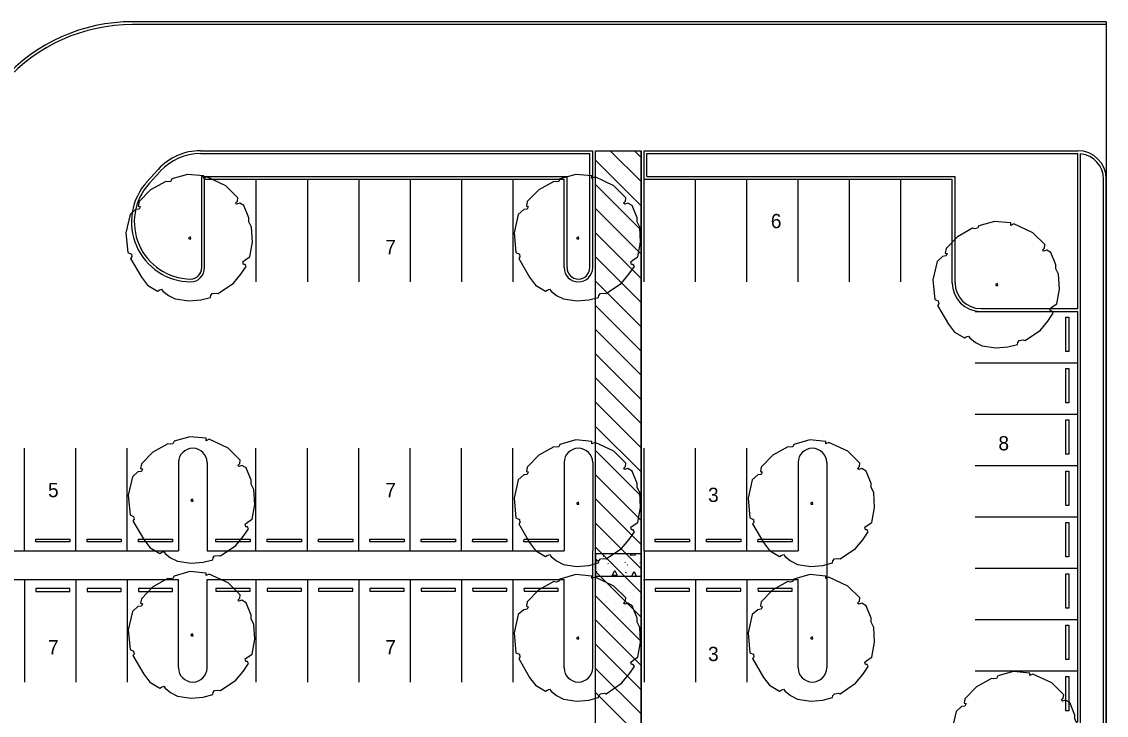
# Model space of a CAD drawing. Extents: x 6712138 to 6712574, y 1869536 to 1870160.
# Drawn here: x 6712370.5 to 6712560.6, y 1870038.8 to 1870160.5 of the extents above; entities that cross this region are included whole.
import ezdxf

# ---------------------------------------------------------------- set-up
doc = ezdxf.new("R2010")
doc.units = 0
for name, color, linetype in [('A-ANNO-TEXT', 7, 'Continuous'), ('A-FLOR-CASE', 7, 'Continuous'), ('A-FLOR-HRAL', 7, 'Continuous'), ('A-FLOR-PATT', 7, 'Continuous'), ('A-WALL-MBNI', 7, 'Continuous'), ('C-Boun-Imaginary', 7, 'Continuous'), ('C-PRKG-CONC', 7, 'Continuous'), ('C-PRKG-STRP', 7, 'Continuous'), ('L-tree', 7, 'Continuous')]:
    doc.layers.add(name, color=color, linetype=linetype)

# ---------------------------------------------------------------- blocks, each defined once
blk = doc.blocks.new('TREE 1')
at = {"layer": 'L-tree'}
for p, q in [((-0.2231, 0.5104), (-0.357, 0.4356)), ((-0.2025, 0.506), (-0.2231, 0.5104)), ((-0.1785, 0.5104), (-0.2025, 0.506)), ((-0.1682, 0.5324), (-0.1785, 0.5104)), ((-0.0275, 0.572), (-0.1682, 0.5324)), ((0.1167, 0.5588), (-0.0275, 0.572)), ((0.1167, 0.5368), (0.1167, 0.5588)), ((0.1441, 0.55), (0.1167, 0.5368)), ((0.3123, 0.4708), (0.1441, 0.55)), ((-0.357, 0.4356), (-0.4599, 0.33)), ((0.4187, 0.3652), (0.3123, 0.4708)), ((-0.4599, 0.33), (-0.4668, 0.2904)), ((-0.4668, 0.2904), (-0.4496, 0.286)), ((0.3981, 0.3168), (0.4153, 0.3344)), ((0.4084, 0.308), (0.3981, 0.3168)), ((0.4359, 0.3168), (0.4084, 0.308)), ((0.4153, 0.3344), (0.4187, 0.3652)), ((0.4737, 0.2948), (0.4359, 0.3168)), ((0.5183, 0.1848), (0.4737, 0.2948)), ((-0.5389, 0.2156), (-0.5766, 0.0528)), ((-0.4908, 0.2596), (-0.5389, 0.2156)), ((-0.4599, 0.264), (-0.4908, 0.2596)), ((-0.4496, 0.286), (-0.4599, 0.264)), ((0.5183, 0.1496), (0.5183, 0.1848)), ((0.5423, 0.1012), (0.5183, 0.1496)), ((0.5492, -0.0308), (0.5423, 0.1012)), ((-0.5766, 0.0528), (-0.5595, -0.1232)), ((-0.0034, 0.0176), (-0.0206, 0.0088)), ((-0.0206, 0.0088), (-0.0137, 0)), ((-0.0137, 0), (0, 0)), ((0, 0), (-0.0034, 0.0176)), ((0.5251, -0.1628), (0.5492, -0.0308)), ((-0.5595, -0.1232), (-0.5286, -0.1364)), ((-0.5251, -0.1628), (-0.5354, -0.176)), ((-0.5354, -0.176), (-0.4393, -0.3432)), ((-0.5286, -0.1364), (-0.5251, -0.1628)), ((0.4634, -0.2068), (0.4839, -0.1892)), ((0.4839, -0.1892), (0.5251, -0.1628)), ((0.4462, -0.3168), (0.4942, -0.2464)), ((0.4702, -0.2288), (0.4634, -0.2068)), ((0.4839, -0.2288), (0.4702, -0.2288)), ((0.4942, -0.2464), (0.4839, -0.2288)), ((-0.4393, -0.3432), (-0.3844, -0.4136)), ((0.381, -0.396), (0.4462, -0.3168)), ((-0.3844, -0.4136), (-0.2952, -0.4664)), ((-0.2952, -0.4664), (-0.2815, -0.4576)), ((-0.2815, -0.4576), (-0.2609, -0.4488)), ((-0.2609, -0.4488), (-0.2471, -0.4664)), ((-0.2471, -0.4664), (-0.1991, -0.506)), ((0.2437, -0.4884), (0.381, -0.396)), ((-0.1991, -0.506), (-0.1373, -0.5368)), ((-0.1373, -0.5368), (-0.0172, -0.5544)), ((-0.0172, -0.5544), (0.0892, -0.5456)), ((0.0892, -0.5456), (0.175, -0.5236)), ((0.175, -0.5236), (0.1785, -0.506)), ((0.1785, -0.506), (0.1922, -0.4884)), ((0.1922, -0.4884), (0.2265, -0.484)), ((0.2265, -0.484), (0.2437, -0.4884))]:
    blk.add_line(p, q, dxfattribs=at)

msp = doc.modelspace()

# ---------------------------------------------------------------- linework, layer by layer
at = {"layer": 'A-FLOR-CASE'}
msp.add_lwpolyline([(6712471.06, 1869725.57), (6712471.06, 1870137.85), (6712479.06, 1870137.85), (6712479.06, 1869725.57)], close=True, dxfattribs=at)
at = {"layer": 'A-FLOR-HRAL'}
msp.add_line((6712560.56, 1870159.97), (6712560.56, 1869926.78), dxfattribs=at)
at = {"layer": 'A-FLOR-PATT'}
for p, q in [((6712472.37, 1870066.79), (6712472.43, 1870066.68)), ((6712476.21, 1870065.78), (6712476.28, 1870065.66)), ((6712478.81, 1870065.68), (6712478.88, 1870065.58)), ((6712471.22, 1870064.02), (6712471.29, 1870064.18)), ((6712473.22, 1870065.5), (6712473.29, 1870065.4)), ((6712476.35, 1870063.84), (6712476.42, 1870064)), ((6712476.59, 1870065.28), (6712476.66, 1870065.17))]:
    msp.add_line(p, q, dxfattribs=at)
for points in [[(6712471.06, 1870066.05), (6712471.13, 1870066.22), (6712471.49, 1870065.95), (6712471.06, 1870065.82)], [(6712473.82, 1870067.1), (6712473.85, 1870067.17)], [(6712474.57, 1870067.17), (6712473.84, 1870067.1)], [(6712477.19, 1870066.88), (6712477.34, 1870067.17)], [(6712477.94, 1870067.17), (6712478.03, 1870066.95), (6712477.21, 1870066.88)], [(6712473.99, 1870063.37), (6712474.46, 1870064.26), (6712474.83, 1870063.44), (6712474.01, 1870063.37)], [(6712477.37, 1870063.17), (6712477.83, 1870064.04), (6712478.2, 1870063.22), (6712477.65, 1870063.17)]]:
    msp.add_lwpolyline(points, dxfattribs=at)
at = {"layer": 'A-WALL-MBNI'}
for p, q in [((6712479.06, 1870067.17), (6712471.06, 1870067.17)), ((6712471.06, 1870067.17), (6712471.06, 1870063.17)), ((6712479.06, 1870067.17), (6712479.06, 1870063.17)), ((6712479.06, 1870063.17), (6712471.06, 1870063.17))]:
    msp.add_line(p, q, dxfattribs=at)
at = {"layer": 'C-Boun-Imaginary'}
msp.add_line((6712560.56, 1870159.97), (6712560.56, 1869926.78), dxfattribs=at)
msp.add_line((6712560.56, 1870159.97), (6712560.56, 1869926.78), dxfattribs=at)
at = {"layer": 'C-PRKG-CONC'}
for p, q in [((6712560.56, 1870160.47), (6712389.92, 1870160.47)), ((6712560.56, 1870159.97), (6712389.92, 1870159.97)), ((6712560.56, 1870160.47), (6712560.56, 1870159.97)), ((6712401.83, 1870137.85), (6712470.56, 1870137.85)), ((6712470.56, 1870132.85), (6712470.56, 1870137.85)), ((6712479.56, 1870132.85), (6712479.56, 1870137.85)), ((6712479.56, 1870137.85), (6712555.56, 1870137.85)), ((6712401.83, 1870137.35), (6712470.06, 1870137.35)), ((6712470.06, 1870117.35), (6712470.06, 1870137.35)), ((6712480.06, 1870133.35), (6712480.06, 1870137.35)), ((6712480.06, 1870137.35), (6712555.56, 1870137.35)), ((6712555.56, 1870110.17), (6712555.56, 1870137.35)), ((6712556.06, 1870037.17), (6712556.06, 1870137.32)), ((6712394.43, 1870134.57), (6712392.46, 1870132.4)), ((6712394.8, 1870134.23), (6712392.83, 1870132.07)), ((6712402.06, 1870133.35), (6712466.06, 1870133.35)), ((6712402.06, 1870117.35), (6712402.06, 1870133.35)), ((6712402.56, 1870132.85), (6712465.56, 1870132.85)), ((6712402.56, 1870117.35), (6712402.56, 1870132.85)), ((6712411.56, 1870132.85), (6712411.56, 1870114.85)), ((6712420.56, 1870132.85), (6712420.56, 1870114.85)), ((6712429.56, 1870132.85), (6712429.56, 1870114.85)), ((6712438.56, 1870132.85), (6712438.56, 1870114.85)), ((6712447.56, 1870132.85), (6712447.56, 1870114.85)), ((6712456.56, 1870132.85), (6712456.56, 1870114.85)), ((6712465.56, 1870117.35), (6712465.56, 1870132.85)), ((6712466.06, 1870117.35), (6712466.06, 1870133.35)), ((6712470.56, 1870117.35), (6712470.56, 1870132.85)), ((6712479.56, 1870132.85), (6712533.56, 1870132.85)), ((6712479.56, 1870114.85), (6712479.56, 1870132.85)), ((6712480.06, 1870133.35), (6712534.06, 1870133.35)), ((6712488.56, 1870114.85), (6712488.56, 1870132.85)), ((6712497.56, 1870114.85), (6712497.56, 1870132.85)), ((6712506.56, 1870114.85), (6712506.56, 1870132.85)), ((6712515.56, 1870114.85), (6712515.56, 1870132.85)), ((6712524.56, 1870114.85), (6712524.56, 1870132.85)), ((6712533.56, 1870114.6), (6712533.56, 1870132.85)), ((6712534.06, 1870114.6), (6712534.06, 1870133.35)), ((6712560.05, 1869930.11), (6712560.06, 1870132.85)), ((6712560.55, 1869930.11), (6712560.56, 1870132.85)), ((6712537.56, 1870109.67), (6712555.56, 1870109.67)), ((6712538.56, 1870110.17), (6712555.56, 1870110.17)), ((6712538.56, 1870109.67), (6712555.56, 1870109.67)), ((6712555.56, 1870037.67), (6712555.56, 1870109.67)), ((6712553.47, 1870108.64), (6712553.97, 1870108.64)), ((6712553.47, 1870102.64), (6712553.47, 1870108.64)), ((6712553.97, 1870108.64), (6712553.97, 1870102.64)), ((6712553.97, 1870102.64), (6712553.47, 1870102.64)), ((6712537.56, 1870100.67), (6712555.56, 1870100.67)), ((6712553.47, 1870099.64), (6712553.97, 1870099.64)), ((6712553.47, 1870093.64), (6712553.47, 1870099.64)), ((6712553.97, 1870099.64), (6712553.97, 1870093.64)), ((6712553.97, 1870093.64), (6712553.47, 1870093.64)), ((6712537.56, 1870091.67), (6712555.56, 1870091.67)), ((6712553.47, 1870090.64), (6712553.97, 1870090.64)), ((6712553.47, 1870084.64), (6712553.47, 1870090.64)), ((6712553.97, 1870090.64), (6712553.97, 1870084.64)), ((6712370.99, 1870067.67), (6712370.99, 1870085.67)), ((6712379.99, 1870067.67), (6712379.99, 1870085.67)), ((6712388.99, 1870067.67), (6712388.99, 1870085.67)), ((6712411.56, 1870067.67), (6712411.56, 1870085.67)), ((6712420.56, 1870067.67), (6712420.56, 1870085.67)), ((6712429.56, 1870067.67), (6712429.56, 1870085.67)), ((6712438.56, 1870067.67), (6712438.56, 1870085.67)), ((6712447.56, 1870067.67), (6712447.56, 1870085.67)), ((6712456.56, 1870067.67), (6712456.56, 1870085.67)), ((6712479.56, 1870067.67), (6712479.56, 1870085.67)), ((6712488.56, 1870067.67), (6712488.56, 1870085.67)), ((6712497.56, 1870067.67), (6712497.56, 1870085.67)), ((6712553.97, 1870084.64), (6712553.47, 1870084.64)), ((6712397.99, 1870083.17), (6712397.99, 1870067.67)), ((6712402.99, 1870083.17), (6712402.99, 1870067.67)), ((6712465.56, 1870083.17), (6712465.56, 1870067.67)), ((6712470.56, 1870083.17), (6712470.56, 1870067.67)), ((6712506.56, 1870083.17), (6712506.56, 1870067.67)), ((6712511.56, 1870083.17), (6712511.56, 1870047.17)), ((6712537.56, 1870082.67), (6712555.56, 1870082.67)), ((6712553.47, 1870081.64), (6712553.97, 1870081.64)), ((6712553.47, 1870075.64), (6712553.47, 1870081.64)), ((6712553.97, 1870081.64), (6712553.97, 1870075.64)), ((6712553.97, 1870075.64), (6712553.47, 1870075.64)), ((6712537.56, 1870073.67), (6712555.56, 1870073.67)), ((6712553.47, 1870072.64), (6712553.97, 1870072.64)), ((6712553.47, 1870066.64), (6712553.47, 1870072.64)), ((6712553.97, 1870072.64), (6712553.97, 1870066.64)), ((6712372.96, 1870069.26), (6712372.96, 1870069.76)), ((6712372.96, 1870069.76), (6712378.96, 1870069.76)), ((6712378.96, 1870069.76), (6712378.96, 1870069.26)), ((6712381.96, 1870069.26), (6712381.96, 1870069.76)), ((6712381.96, 1870069.76), (6712387.96, 1870069.76)), ((6712387.96, 1870069.76), (6712387.96, 1870069.26)), ((6712390.96, 1870069.26), (6712390.96, 1870069.76)), ((6712390.96, 1870069.76), (6712396.96, 1870069.76)), ((6712396.96, 1870069.76), (6712396.96, 1870069.26)), ((6712404.52, 1870069.26), (6712404.53, 1870069.76)), ((6712404.53, 1870069.76), (6712410.53, 1870069.76)), ((6712410.53, 1870069.76), (6712410.52, 1870069.26)), ((6712413.52, 1870069.26), (6712413.53, 1870069.76)), ((6712413.53, 1870069.76), (6712419.53, 1870069.76)), ((6712419.53, 1870069.76), (6712419.52, 1870069.26)), ((6712422.52, 1870069.26), (6712422.53, 1870069.76)), ((6712422.53, 1870069.76), (6712428.53, 1870069.76)), ((6712428.53, 1870069.76), (6712428.52, 1870069.26)), ((6712431.52, 1870069.26), (6712431.53, 1870069.76)), ((6712431.53, 1870069.76), (6712437.53, 1870069.76)), ((6712437.53, 1870069.76), (6712437.52, 1870069.26)), ((6712440.52, 1870069.26), (6712440.53, 1870069.76)), ((6712440.53, 1870069.76), (6712446.53, 1870069.76)), ((6712446.53, 1870069.76), (6712446.52, 1870069.26)), ((6712449.52, 1870069.26), (6712449.53, 1870069.76)), ((6712449.53, 1870069.76), (6712455.53, 1870069.76)), ((6712455.53, 1870069.76), (6712455.52, 1870069.26)), ((6712458.52, 1870069.26), (6712458.53, 1870069.76)), ((6712458.53, 1870069.76), (6712464.53, 1870069.76)), ((6712464.53, 1870069.76), (6712464.52, 1870069.26)), ((6712481.52, 1870069.26), (6712481.53, 1870069.76)), ((6712481.53, 1870069.76), (6712487.53, 1870069.76)), ((6712487.53, 1870069.76), (6712487.52, 1870069.26)), ((6712490.52, 1870069.26), (6712490.53, 1870069.76)), ((6712490.53, 1870069.76), (6712496.53, 1870069.76)), ((6712496.53, 1870069.76), (6712496.52, 1870069.26)), ((6712499.52, 1870069.26), (6712499.53, 1870069.76)), ((6712499.53, 1870069.76), (6712505.53, 1870069.76)), ((6712505.53, 1870069.76), (6712505.52, 1870069.26)), ((6712352.99, 1870067.67), (6712397.99, 1870067.67)), ((6712378.96, 1870069.26), (6712372.96, 1870069.26)), ((6712387.96, 1870069.26), (6712381.96, 1870069.26)), ((6712396.96, 1870069.26), (6712390.96, 1870069.26)), ((6712402.99, 1870067.67), (6712465.56, 1870067.67)), ((6712410.52, 1870069.26), (6712404.52, 1870069.26)), ((6712419.52, 1870069.26), (6712413.52, 1870069.26)), ((6712428.52, 1870069.26), (6712422.52, 1870069.26)), ((6712437.52, 1870069.26), (6712431.52, 1870069.26)), ((6712446.52, 1870069.26), (6712440.52, 1870069.26)), ((6712455.52, 1870069.26), (6712449.52, 1870069.26)), ((6712464.52, 1870069.26), (6712458.52, 1870069.26)), ((6712470.56, 1870047.17), (6712470.56, 1870067.67)), ((6712479.56, 1870067.67), (6712479.56, 1870044.67)), ((6712479.56, 1870067.67), (6712506.56, 1870067.67)), ((6712487.52, 1870069.26), (6712481.52, 1870069.26)), ((6712496.52, 1870069.26), (6712490.52, 1870069.26)), ((6712505.52, 1870069.26), (6712499.52, 1870069.26)), ((6712553.97, 1870066.64), (6712553.47, 1870066.64)), ((6712537.56, 1870064.67), (6712555.56, 1870064.67)), ((6712334.99, 1870062.67), (6712397.99, 1870062.67)), ((6712370.99, 1870062.67), (6712370.99, 1870044.67)), ((6712379.99, 1870062.67), (6712379.99, 1870044.67)), ((6712388.99, 1870062.67), (6712388.99, 1870044.67)), ((6712397.99, 1870047.17), (6712397.99, 1870062.67)), ((6712402.99, 1870062.67), (6712465.56, 1870062.67)), ((6712402.99, 1870047.17), (6712402.99, 1870062.67)), ((6712411.56, 1870062.67), (6712411.56, 1870044.67)), ((6712420.56, 1870062.67), (6712420.56, 1870044.67)), ((6712429.56, 1870062.67), (6712429.56, 1870044.67)), ((6712438.56, 1870062.67), (6712438.56, 1870044.67)), ((6712447.56, 1870062.67), (6712447.56, 1870044.67)), ((6712456.56, 1870062.67), (6712456.56, 1870044.67)), ((6712465.56, 1870047.17), (6712465.56, 1870062.67)), ((6712479.45, 1870062.67), (6712506.56, 1870062.67)), ((6712488.56, 1870062.67), (6712488.56, 1870044.67)), ((6712497.56, 1870062.67), (6712497.56, 1870044.67)), ((6712506.56, 1870047.17), (6712506.56, 1870062.67)), ((6712553.47, 1870063.64), (6712553.97, 1870063.64)), ((6712553.47, 1870057.64), (6712553.47, 1870063.64)), ((6712553.97, 1870063.64), (6712553.97, 1870057.64)), ((6712372.96, 1870061.08), (6712372.96, 1870060.58)), ((6712378.96, 1870061.08), (6712372.96, 1870061.08)), ((6712372.96, 1870060.58), (6712378.96, 1870060.58)), ((6712378.96, 1870060.58), (6712378.96, 1870061.08)), ((6712381.96, 1870061.08), (6712381.96, 1870060.58)), ((6712387.96, 1870061.08), (6712381.96, 1870061.08)), ((6712381.96, 1870060.58), (6712387.96, 1870060.58)), ((6712387.96, 1870060.58), (6712387.96, 1870061.08)), ((6712390.96, 1870061.08), (6712390.96, 1870060.58)), ((6712396.96, 1870061.08), (6712390.96, 1870061.08)), ((6712390.96, 1870060.58), (6712396.96, 1870060.58)), ((6712396.96, 1870060.58), (6712396.96, 1870061.08)), ((6712404.52, 1870061.09), (6712404.53, 1870060.59)), ((6712410.52, 1870061.09), (6712404.52, 1870061.09)), ((6712404.53, 1870060.59), (6712410.53, 1870060.59)), ((6712410.53, 1870060.59), (6712410.52, 1870061.09)), ((6712413.52, 1870061.09), (6712413.53, 1870060.59)), ((6712419.52, 1870061.09), (6712413.52, 1870061.09)), ((6712413.53, 1870060.59), (6712419.53, 1870060.59)), ((6712419.53, 1870060.59), (6712419.52, 1870061.09)), ((6712422.52, 1870061.09), (6712422.53, 1870060.59)), ((6712428.52, 1870061.09), (6712422.52, 1870061.09)), ((6712422.53, 1870060.59), (6712428.53, 1870060.59)), ((6712428.53, 1870060.59), (6712428.52, 1870061.09)), ((6712431.52, 1870061.09), (6712431.53, 1870060.59)), ((6712437.52, 1870061.09), (6712431.52, 1870061.09)), ((6712431.53, 1870060.59), (6712437.53, 1870060.59)), ((6712437.53, 1870060.59), (6712437.52, 1870061.09)), ((6712440.52, 1870061.09), (6712440.53, 1870060.59)), ((6712446.52, 1870061.09), (6712440.52, 1870061.09)), ((6712440.53, 1870060.59), (6712446.53, 1870060.59)), ((6712446.53, 1870060.59), (6712446.52, 1870061.09)), ((6712449.52, 1870061.09), (6712449.53, 1870060.59)), ((6712455.52, 1870061.09), (6712449.52, 1870061.09)), ((6712449.53, 1870060.59), (6712455.53, 1870060.59)), ((6712455.53, 1870060.59), (6712455.52, 1870061.09)), ((6712458.52, 1870061.09), (6712458.53, 1870060.59)), ((6712464.52, 1870061.09), (6712458.52, 1870061.09)), ((6712458.53, 1870060.59), (6712464.53, 1870060.59)), ((6712464.53, 1870060.59), (6712464.52, 1870061.09)), ((6712481.52, 1870061.09), (6712481.53, 1870060.59)), ((6712487.52, 1870061.09), (6712481.52, 1870061.09)), ((6712481.53, 1870060.59), (6712487.53, 1870060.59)), ((6712487.53, 1870060.59), (6712487.52, 1870061.09)), ((6712490.52, 1870061.09), (6712490.53, 1870060.59)), ((6712496.52, 1870061.09), (6712490.52, 1870061.09)), ((6712490.53, 1870060.59), (6712496.53, 1870060.59)), ((6712496.53, 1870060.59), (6712496.52, 1870061.09)), ((6712499.52, 1870061.09), (6712499.53, 1870060.59)), ((6712505.52, 1870061.09), (6712499.52, 1870061.09)), ((6712499.53, 1870060.59), (6712505.53, 1870060.59)), ((6712505.53, 1870060.59), (6712505.52, 1870061.09)), ((6712553.97, 1870057.64), (6712553.47, 1870057.64)), ((6712537.56, 1870055.67), (6712555.56, 1870055.67)), ((6712553.47, 1870054.64), (6712553.97, 1870054.64)), ((6712553.47, 1870048.64), (6712553.47, 1870054.64)), ((6712553.97, 1870054.64), (6712553.97, 1870048.64)), ((6712553.97, 1870048.64), (6712553.47, 1870048.64)), ((6712537.56, 1870046.67), (6712555.56, 1870046.67)), ((6712553.47, 1870045.64), (6712553.97, 1870045.64)), ((6712553.47, 1870039.64), (6712553.47, 1870045.64)), ((6712553.97, 1870045.64), (6712553.97, 1870039.64)), ((6712553.97, 1870039.64), (6712553.47, 1870039.64))]:
    msp.add_line(p, q, dxfattribs=at)
for centre, radius, start, end in [((6712389.92, 1870129.97), 30.5, 90, 138.1293), ((6712389.92, 1870129.97), 30, 90, 138.1293), ((6712401.83, 1870127.85), 10, 90, 137.7596), ((6712555.56, 1870132.85), 5, 360, 90), ((6712401.83, 1870127.85), 9.5, 90, 137.7596), ((6712555.56, 1870132.85), 4.5, 360, 83.6207), ((6712400.24, 1870125.35), 10.5, 137.7596, 269.2341), ((6712400.24, 1870125.35), 10, 137.7596, 269.2341), ((6712400.06, 1870117.35), 2, 270.727, 0), ((6712400.06, 1870117.35), 2.5, 270.727, 0), ((6712468.06, 1870117.35), 2.5, 180, 360), ((6712468.06, 1870117.35), 2, 180, 360), ((6712538.56, 1870114.67), 5, 180, 270), ((6712538.56, 1870114.67), 4.5, 180, 270), ((6712400.49, 1870083.17), 2.5, 0, 180), ((6712468.06, 1870083.17), 2.5, 0, 180), ((6712509.06, 1870083.17), 2.5, 0, 180), ((6712400.49, 1870047.17), 2.5, 180, 360), ((6712468.06, 1870047.17), 2.5, 180, 360), ((6712509.06, 1870047.17), 2.5, 180, 360)]:
    msp.add_arc(centre, radius, start, end, dxfattribs=at)
at = {"layer": 'C-PRKG-STRP'}
for p, q in [((6712471.06, 1870137.85), (6712479.06, 1870137.85)), ((6712471.06, 1869890.59), (6712471.06, 1870137.85)), ((6712479.06, 1870132.42), (6712473.63, 1870137.85)), ((6712479.06, 1870136.67), (6712477.88, 1870137.85)), ((6712479.06, 1869890.59), (6712479.06, 1870137.85)), ((6712479.06, 1870128.18), (6712471.06, 1870136.18)), ((6712479.06, 1870123.94), (6712471.06, 1870131.94)), ((6712479.06, 1870119.7), (6712471.06, 1870127.7)), ((6712479.06, 1870115.45), (6712471.06, 1870123.45)), ((6712479.06, 1870111.21), (6712471.06, 1870119.21)), ((6712479.06, 1870106.97), (6712471.06, 1870114.97)), ((6712479.06, 1870102.72), (6712471.06, 1870110.72)), ((6712479.06, 1870098.48), (6712471.06, 1870106.48)), ((6712479.06, 1870094.24), (6712471.06, 1870102.24)), ((6712479.06, 1870090), (6712471.06, 1870098)), ((6712479.06, 1870085.75), (6712471.06, 1870093.75)), ((6712479.06, 1870081.51), (6712471.06, 1870089.51)), ((6712479.06, 1870077.27), (6712471.06, 1870085.27)), ((6712479.06, 1870073.03), (6712471.06, 1870081.03)), ((6712479.06, 1870068.78), (6712471.06, 1870076.78)), ((6712479.06, 1870064.54), (6712471.06, 1870072.54)), ((6712479.06, 1870060.3), (6712471.06, 1870068.3)), ((6712479.06, 1870056.06), (6712471.06, 1870064.06)), ((6712479.06, 1870051.81), (6712471.06, 1870059.81)), ((6712479.06, 1870047.57), (6712471.06, 1870055.57)), ((6712479.06, 1870043.33), (6712471.06, 1870051.33)), ((6712479.06, 1870039.08), (6712471.06, 1870047.08)), ((6712479.06, 1870034.84), (6712471.06, 1870042.84))]:
    msp.add_line(p, q, dxfattribs=at)

# ---------------------------------------------------------------- block references
at = {"layer": 'L-tree', "xscale": 19.68503937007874, "yscale": 19.68503937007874}
for p in [(6712400.13, 1870122.42), (6712468.13, 1870122.42), (6712541.53, 1870114.19), (6712400.53, 1870076.42), (6712468.13, 1870075.88), (6712509.13, 1870075.88), (6712400.53, 1870052.79), (6712468.13, 1870052.25), (6712509.13, 1870052.25), (6712544.85, 1870035.26)]:
    msp.add_blockref('TREE 1', p, dxfattribs=at)

# ---------------------------------------------------------------- texts
at = {"layer": 'A-ANNO-TEXT'}
for s, p in [('6', (6712501.78, 1870124.26)), ('7', (6712434.22, 1870119.7)), ('8', (6712541.66, 1870085.3)), ('5', (6712375.13, 1870077.09)), ('7', (6712434.22, 1870077.09)), ('3', (6712490.78, 1870076.25)), ('7', (6712375.13, 1870049.53)), ('7', (6712434.22, 1870049.53)), ('3', (6712490.78, 1870048.36))]:
    msp.add_text(s, height=2.5, rotation=0.2528, dxfattribs=at).set_placement(p)

doc.saveas('drawing.dxf')
